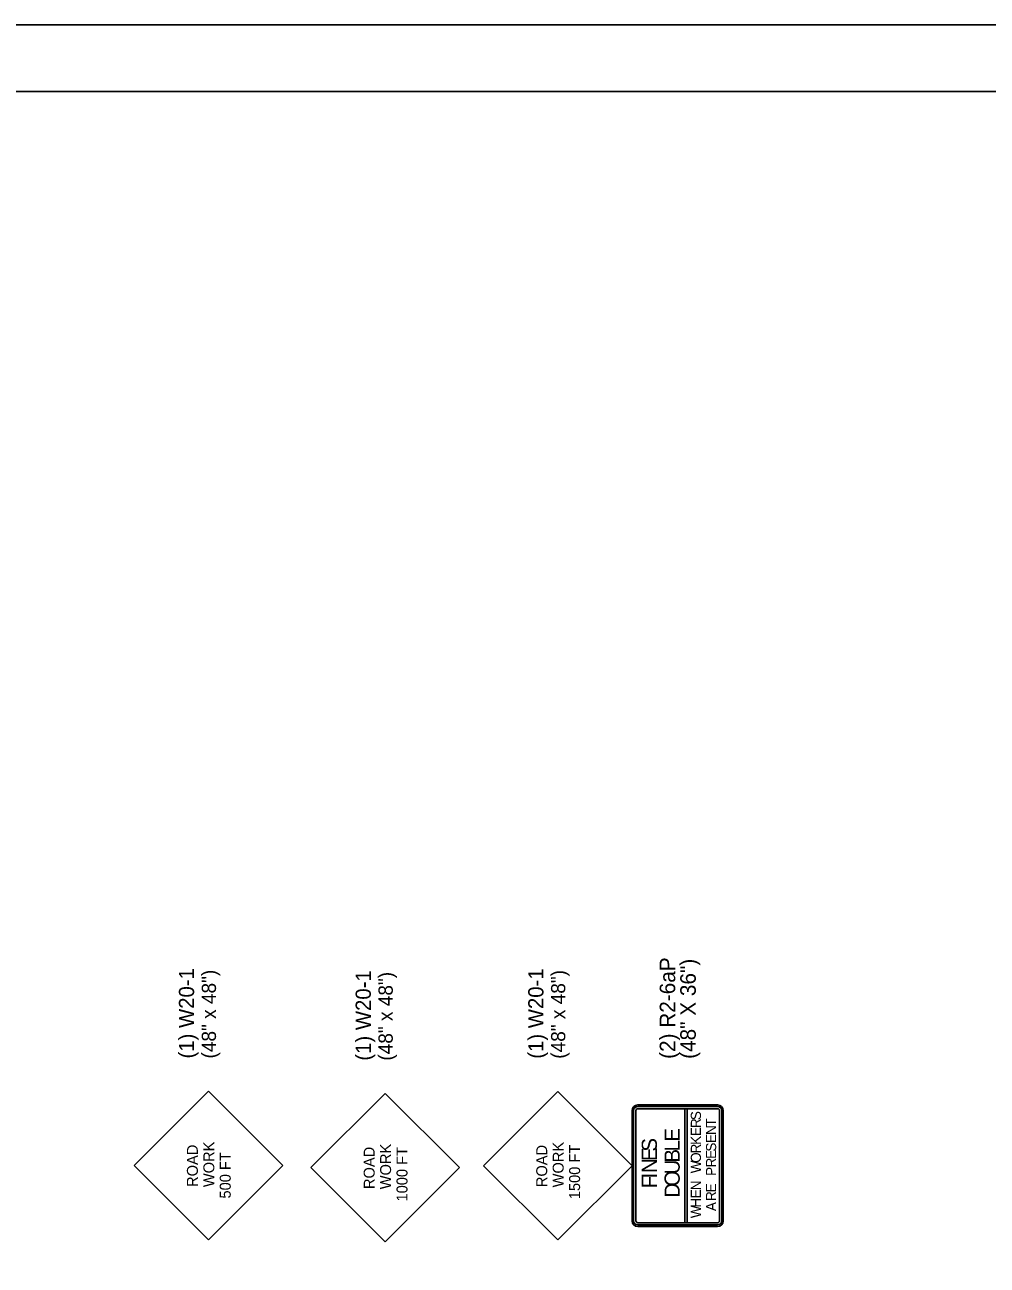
# Model space of a CAD drawing. Extents: x 32485 to 39285, y 55121 to 58033.
# Drawn here: x 36848.1 to 37209.5, y 57398 to 57863.9 of the extents above; entities that cross this region are included whole.
import ezdxf

# ---------------------------------------------------------------- set-up
doc = ezdxf.new("R2010")
doc.units = 0
for name, color, linetype in [('Default', 7, 'Continuous'), ('R_Border', 7, 'Continuous'), ('R_Border Notes', 7, 'Continuous'), ('R_Draft', 7, 'Continuous')]:
    doc.layers.add(name, color=color, linetype=linetype)

msp = doc.modelspace()

# ---------------------------------------------------------------- linework, layer by layer
at = {"layer": 'Default'}
for p, q in [((37076.16, 57456.07), (37076.16, 57414.67)), ((37076.75, 57456.07), (37076.75, 57414.67)), ((37077.59, 57414.67), (37077.59, 57456.07)), ((37108.28, 57458.21), (37078.3, 57458.21)), ((37108.28, 57457.62), (37078.3, 57457.62)), ((37078.3, 57456.78), (37108.28, 57456.78)), ((37095.97, 57413.96), (37095.97, 57456.78)), ((37095.97, 57456.78), (37096.8, 57456.78)), ((37096.8, 57456.78), (37096.8, 57413.96)), ((37108.99, 57456.07), (37108.99, 57414.67)), ((37109.83, 57414.67), (37109.83, 57456.07)), ((37110.42, 57414.67), (37110.42, 57456.07)), ((37108.28, 57413.96), (37078.3, 57413.96)), ((37078.3, 57413.12), (37108.28, 57413.12)), ((37078.3, 57412.53), (37108.28, 57412.53)), ((37096.8, 57413.96), (37095.97, 57413.96))]:
    msp.add_line(p, q, dxfattribs=at)
msp.add_lwpolyline([(35885, 57863.91), (35885, 56763.91), (37585, 56763.91), (37585, 57863.91)], close=True, dxfattribs=at)
for centre, radius, start, end in [((37078.3, 57456.07), 2.14, 90, 180), ((37078.3, 57456.07), 1.55, 90, 180), ((37078.3, 57456.07), 0.714, 90, 180), ((37108.28, 57456.07), 2.14, 0, 90), ((37108.28, 57456.07), 1.55, 0, 90), ((37108.28, 57456.07), 0.714, 0, 90), ((37078.3, 57414.67), 2.14, 180, 270), ((37078.3, 57414.67), 1.55, 180, 270), ((37078.3, 57414.67), 0.714, 180, 270), ((37108.28, 57414.67), 2.14, 270, 0), ((37108.28, 57414.67), 1.55, 270, 0), ((37108.28, 57414.67), 0.714, 270, 0)]:
    msp.add_arc(centre, radius, start, end, dxfattribs=at)
at = {"layer": 'R_Border'}
for p, q in [((36917.11, 57463.36), (36889.21, 57435.46)), ((36917.11, 57463.36), (36944.99, 57435.46)), ((36983.48, 57462.55), (36955.58, 57434.66)), ((36983.48, 57462.55), (37011.36, 57434.66)), ((37048.28, 57463.27), (37020.38, 57435.37)), ((37048.28, 57463.27), (37076.16, 57435.37)), ((36889.21, 57435.46), (36917.11, 57407.56)), ((36944.99, 57435.46), (36917.11, 57407.56)), ((36955.58, 57434.66), (36983.48, 57406.76)), ((37011.36, 57434.66), (36983.48, 57406.76)), ((37020.38, 57435.37), (37048.28, 57407.47)), ((37076.16, 57435.37), (37048.28, 57407.47))]:
    msp.add_line(p, q, dxfattribs=at)
at = {"layer": 'R_Border Notes'}
for points in [[(35885, 56763.91), (37585, 56763.91), (37585, 57863.91), (35885, 57863.91)], [(35910, 56788.91), (37560, 56788.91), (37560, 57838.91), (35910, 57838.91)]]:
    msp.add_lwpolyline(points, close=True, dxfattribs=at)

# ---------------------------------------------------------------- texts
at = {"layer": 'Default'}
for s, height, p in [('S', 3.81, (37102.03, 57452.48)), ('R', 3.81, (37102.03, 57449.51)), ('T', 3.81, (37107.74, 57450.07)), ('E', 5.71, (37094.06, 57444.45)), ('E', 3.81, (37102.03, 57446.51)), ('N', 3.81, (37107.74, 57446.91)), ('E', 3.81, (37107.74, 57443.9)), ('S', 5.71, (37085.5, 57440.68)), ('L', 5.71, (37094.06, 57440.74)), ('K', 3.81, (37102.03, 57443.19)), ('R', 3.81, (37102.03, 57439.96)), ('S', 3.81, (37107.74, 57440.66)), ('E', 5.71, (37085.5, 57437.08)), ('N', 5.71, (37085.5, 57432.63)), ('B', 5.71, (37094.06, 57436.57)), ('O', 3.81, (37102.03, 57436.42)), ('E', 3.81, (37107.74, 57437.92)), ('R', 3.81, (37107.74, 57434.68)), ('O', 5.71, (37094.06, 57427.6)), ('U', 5.71, (37094.06, 57432.12)), ('W', 3.81, (37102.03, 57432.53)), ('P', 3.81, (37107.74, 57431.53)), ('I', 5.71, (37085.5, 57430.57)), ('F', 5.71, (37085.5, 57426.86)), ('D', 5.71, (37094.06, 57423.38)), ('N', 3.81, (37102.03, 57426.14)), ('E', 3.81, (37107.74, 57425.36)), ('E', 3.81, (37102.03, 57423.13)), ('R', 3.81, (37107.74, 57422.12)), ('H', 3.81, (37102.03, 57419.63)), ('W', 3.81, (37102.03, 57415.67)), ('A', 3.81, (37107.74, 57418.31))]:
    msp.add_text(s, height=height, rotation=90, dxfattribs=at).set_placement(p)
at = {"layer": 'R_Border'}
for s, height, rotation, p in [('(1) W20-1', 5.71, 90, (36911.71, 57475.64)), ('(48" x 48")', 5.3523, 90, (36919.93, 57475.64)), ('(1) W20-1', 5.71, 90, (36978.08, 57474.83)), ('(48" x 48")', 5.3523, 90, (36986.3, 57474.83)), ('(1) W20-1', 5.71, 90, (37042.88, 57475.55)), ('(48" x 48")', 5.3523, 90, (37051.09, 57475.55)), ('ROAD', 4.11, 90.0004, (36913.13, 57427.4)), ('WORK', 4.11, 90, (36919.3, 57427.32)), ('ROAD', 4.11, 90.0004, (36979.51, 57426.6)), ('WORK', 4.11, 90, (36985.67, 57426.52)), ('1000 FT', 4.11, 90.0006, (36991.84, 57421.92)), ('ROAD', 4.11, 90.0004, (37044.3, 57427.31)), ('WORK', 4.11, 90, (37050.47, 57427.23)), ('1500 FT', 4.11, 90.0006, (37056.64, 57422.79)), (' 500 FT', 4.11, 90.0006, (36925.46, 57421.51))]:
    msp.add_text(s, height=height, rotation=rotation, dxfattribs=at).set_placement(p)
at = {"layer": 'R_Draft'}
for s, height, p in [('(2) R2-6aP', 5.83, (37092.37, 57475.5)), ('(48" X 36")', 5.8301, (37100.09, 57475.5))]:
    msp.add_text(s, height=height, rotation=90, dxfattribs=at).set_placement(p)

doc.saveas('drawing.dxf')
